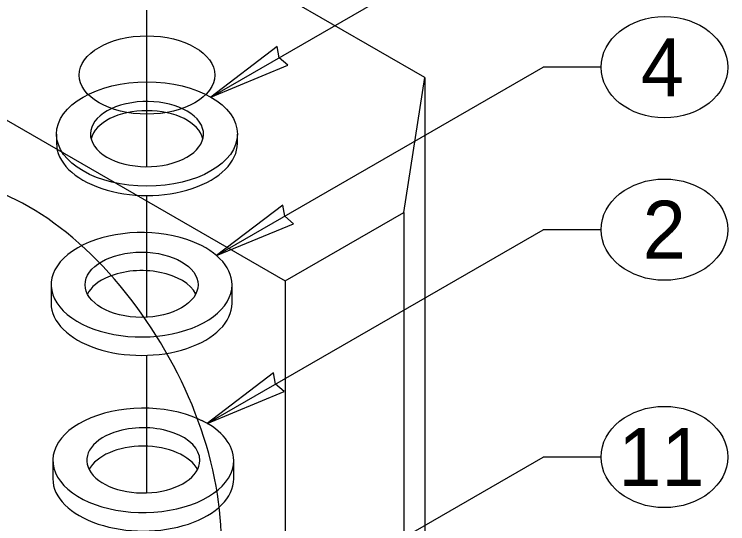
# Model space of a CAD drawing. Extents: x 99862 to 104211, y 98939 to 105076.
# Drawn here: x 101481.1 to 101678.3, y 101758.7 to 101899.6 of the extents above; entities that cross this region are included whole.
import ezdxf

# ---------------------------------------------------------------- set-up
doc = ezdxf.new("R2010")
doc.units = 0
for name, color, linetype in [('Level 11', 7, 'Continuous'), ('Level 15', 7, 'Continuous'), ('Level 2', 7, 'Continuous'), ('Level 20', 7, 'Continuous'), ('Level 26', 7, 'Continuous'), ('Level 4', 7, 'Continuous'), ('Level 5', 7, 'Continuous')]:
    doc.layers.add(name, color=color, linetype=linetype)

msp = doc.modelspace()

# ---------------------------------------------------------------- linework, layer by layer
at = {"layer": 'Level 11'}
for start_param, end_param in [(0, 2.024427), (2.024427, 6.283185)]:
    msp.add_ellipse((101516.75, 101776.27), major_axis=(15.62, 0), ratio=0.57735, start_param=start_param, end_param=end_param, dxfattribs=at)
at = {"layer": 'Level 15'}
for p, q in [((101535.45, 101876.72), (101627.26, 101929.72)), ((101517.77, 101857.49), (101517.77, 101900.8)), ((101537.02, 101832.89), (101627.26, 101884.99)), ((101643.26, 101884.99), (101627.26, 101884.99)), ((101517.77, 101815.86), (101517.77, 101849.53)), ((101534.43, 101786.48), (101627.26, 101840.07)), ((101643.26, 101840.07), (101627.26, 101840.07)), ((101517.77, 101767.27), (101517.77, 101805.33)), ((101535.45, 101724.2), (101627.26, 101777.2)), ((101643.26, 101777.2), (101627.26, 101777.2))]:
    msp.add_line(p, q, dxfattribs=at)
for points in [[(101535.45, 101876.72), (101556.71, 101885.55), (101554.31, 101887.61), (101553.73, 101890.72)], [(101537.02, 101832.89), (101558.29, 101841.72), (101555.88, 101843.78), (101555.3, 101846.89)], [(101534.43, 101786.48), (101555.69, 101795.31), (101553.29, 101797.37), (101552.71, 101800.48)]]:
    msp.add_lwpolyline(points, close=True, dxfattribs=at)
at = {"layer": 'Level 2'}
for p, q in [((101491.75, 101776.27), (101491.75, 101771.17)), ((101541.75, 101771.17), (101541.75, 101776.27))]:
    msp.add_line(p, q, dxfattribs=at)
for centre, major_axis, start_param, end_param in [((101516.75, 101776.27), (25, 0), 0.825055, 6.283185), ((101516.75, 101776.27), (25, 0), 6.283185, 7.149233), ((101516.75, 101771.17), (-15.62, 0), 3.428349, 5.996429), ((101516.75, 101771.17), (-25, 0), 0, 3.141593)]:
    msp.add_ellipse(centre, major_axis=major_axis, ratio=0.57735, start_param=start_param, end_param=end_param, dxfattribs=at)
at = {"layer": 'Level 20'}
for centre in [(101660.76, 101884.99), (101660.76, 101840.07), (101660.76, 101777.2)]:
    msp.add_ellipse(centre, major_axis=(-17.5, 0), ratio=0.8, dxfattribs=at)
at = {"layer": 'Level 26'}
for p, q in [((101594.59, 101882.14), (101532.07, 101918.24)), ((101414.53, 101907.58), (101555.95, 101825.93)), ((101588.71, 101844.85), (101594.59, 101882.14)), ((101594.59, 101882.14), (101594.59, 101712.58)), ((101555.95, 101825.93), (101588.71, 101844.85)), ((101588.71, 101844.85), (101588.71, 101675.29)), ((101555.95, 101825.93), (101555.95, 101656.37))]:
    msp.add_line(p, q, dxfattribs=at)
msp.add_ellipse((101517.77, 101882.84), major_axis=(18.75, 0), ratio=0.57735, dxfattribs=at)
msp.add_ellipse((101485.24, 101785.11), major_axis=(37.5, -64.95), ratio=0.57735, start_param=0, end_param=3.141593, dxfattribs=at)
at = {"layer": 'Level 4'}
for p, q in [((101491.28, 101824.84), (101491.28, 101819.73)), ((101541.28, 101819.73), (101541.28, 101824.84))]:
    msp.add_line(p, q, dxfattribs=at)
for centre, major_axis, start_param, end_param in [((101516.28, 101824.84), (25, 0), 1.046133, 6.283185), ((101516.28, 101824.84), (25, 0), 6.283185, 7.329318), ((101516.28, 101819.73), (-15.62, 0), 3.428349, 5.340377), ((101516.28, 101819.73), (-15.62, 0), 5.340377, 5.996429), ((101516.28, 101819.73), (-25, 0), 6.283185, 9.424778)]:
    msp.add_ellipse(centre, major_axis=major_axis, ratio=0.57735, start_param=start_param, end_param=end_param, dxfattribs=at)
msp.add_ellipse((101516.28, 101824.84), major_axis=(15.62, 0), ratio=0.57735, dxfattribs=at)
at = {"layer": 'Level 5'}
for p, q in [((101512.03, 101874.9), (101511.9, 101874.87)), ((101492.77, 101866.51), (101492.77, 101863.96)), ((101542.77, 101863.96), (101542.77, 101866.51))]:
    msp.add_line(p, q, dxfattribs=at)
msp.add_ellipse((101517.77, 101866.51), major_axis=(25, 0), ratio=0.57735, dxfattribs=at)
for centre, major_axis, start_param, end_param in [((101517.77, 101866.51), (15.62, 0), 1.95592, 8.230034), ((101517.77, 101863.96), (-15.62, 0), 3.28349, 6.141288), ((101517.77, 101863.96), (-25, 0), 6.283185, 9.424778)]:
    msp.add_ellipse(centre, major_axis=major_axis, ratio=0.57735, start_param=start_param, end_param=end_param, dxfattribs=at)

# ---------------------------------------------------------------- texts
at = {"layer": 'Level 20'}
for s, p in [('4', (101654.25, 101876.99)), ('2', (101654.77, 101832.08)), ('11', (101648.03, 101769.2))]:
    msp.add_text(s, height=16, dxfattribs=at).set_placement(p)

doc.saveas('drawing.dxf')
